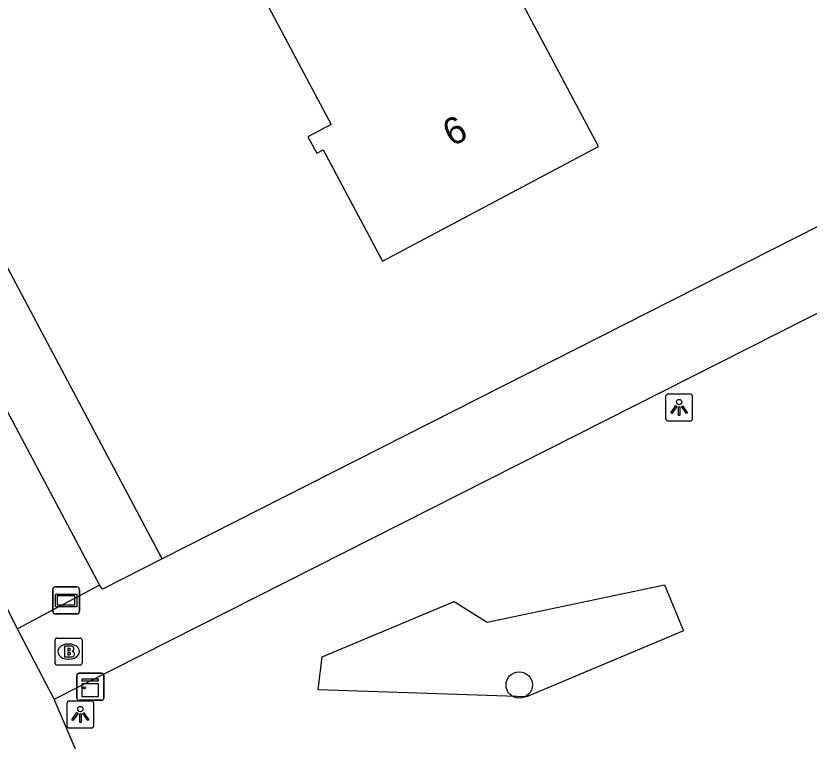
# Model space of a CAD drawing. Extents: x 162417 to 163721, y 384268 to 385416.
# Drawn here: x 163573.8 to 163603.15, y 384788.06 to 384814.9 of the extents above; entities that cross this region are included whole.
import ezdxf

# ---------------------------------------------------------------- set-up
doc = ezdxf.new("R2010")
doc.units = 0
for name, color, linetype in [('IMGEO_Boom', 7, 'Continuous'), ('IMGEO_Brandkraan', 7, 'Continuous'), ('IMGEO_Groenvoorziening', 7, 'Continuous'), ('IMGEO_Kast', 7, 'Continuous'), ('IMGEO_Lichtpunt', 7, 'Continuous'), ('IMGEO_Pand', 7, 'Continuous'), ('IMGEO_Pand_nummerreeks', 7, 'Continuous'), ('IMGEO_Rijbaan_lokaal_gesloten', 7, 'Continuous'), ('IMGEO_Verklikker', 7, 'Continuous'), ('IMGEO_Voetpad_open', 7, 'Continuous')]:
    doc.layers.add(name, color=color, linetype=linetype)

msp = doc.modelspace()

# ---------------------------------------------------------------- linework, layer by layer
at = {"layer": 'IMGEO_Boom'}
msp.add_circle((163592.424, 384790.139), 0.489, dxfattribs=at)
at = {"layer": 'IMGEO_Brandkraan'}
for p, q in [((163575.325, 384791.875), (163576.177, 384791.875)), ((163575.25, 384790.949), (163575.25, 384791.801)), ((163575.738, 384791.655), (163575.763, 384791.655)), ((163576.251, 384791.801), (163576.251, 384790.949)), ((163575.761, 384791.095), (163575.736, 384791.095)), ((163576.177, 384790.875), (163575.325, 384790.875))]:
    msp.add_line(p, q, dxfattribs=at)
for points in [[(163575.325, 384791.875), (163576.177, 384791.875)], [(163575.25, 384790.949), (163575.25, 384791.801)], [(163575.598, 384791.575), (163575.598, 384791.175), (163575.811, 384791.175)], [(163575.829, 384791.575), (163575.598, 384791.575)], [(163576.251, 384791.801), (163576.251, 384790.949)], [(163575.777, 384791.494), (163575.723, 384791.494), (163575.723, 384791.418)], [(163575.723, 384791.418), (163575.776, 384791.418)], [(163575.785, 384791.342), (163575.723, 384791.342), (163575.723, 384791.261)], [(163575.723, 384791.261), (163575.785, 384791.261)], [(163576.177, 384790.875), (163575.325, 384790.875)]]:
    msp.add_lwpolyline(points, dxfattribs=at)
for centre, radius, start, end in [((163575.327, 384791.799), 0.0765, 91.552, 178.448), ((163575.327, 384791.799), 0.0765, 91.552, 178.448), ((163576.175, 384791.799), 0.0765, 1.552, 88.448), ((163576.175, 384791.799), 0.0765, 1.552, 88.448), ((163575.833, 384791.43), 0.145, 59.4692, 91.5367), ((163575.858, 384791.477), 0.0922, 285.5137, 58.1501), ((163575.778, 384791.456), 0.0379, 267.8285, 90.9355), ((163575.786, 384791.301), 0.0404, 269.8759, 90.5077), ((163575.863, 384791.285), 0.105, 301.3115, 78.989), ((163575.817, 384791.426), 0.251, 268.6676, 293.5347), ((163575.327, 384790.951), 0.0765, 181.552, 268.448), ((163575.327, 384790.951), 0.0765, 181.552, 268.448), ((163576.175, 384790.951), 0.0765, 271.552, 358.448), ((163576.175, 384790.951), 0.0765, 271.552, 358.448)]:
    msp.add_arc(centre, radius, start, end, dxfattribs=at)
for centre, major_axis, ratio, start_param, end_param in [((163575.737, 384791.375), (-0.387, 0.002), 0.722429, 4.712389, 7.853982), ((163575.762, 384791.375), (-0.39, 0.002), 0.717154, 1.570796, 4.712389)]:
    msp.add_ellipse(centre, major_axis=major_axis, ratio=ratio, start_param=start_param, end_param=end_param, dxfattribs=at)
at = {"layer": 'IMGEO_Groenvoorziening'}
msp.add_lwpolyline([(163592.689, 384789.696), (163584.983, 384789.965), (163585.127, 384791.183), (163590.02, 384793.225), (163591.241, 384792.459), (163597.802, 384793.844), (163598.502, 384792.145), (163592.689, 384789.696)], dxfattribs=at)
at = {"layer": 'IMGEO_Kast'}
for p, q in [((163576.056, 384789.648), (163576.056, 384790.489)), ((163576.056, 384790.489), (163576.056, 384789.648)), ((163576.131, 384790.573), (163576.972, 384790.573)), ((163576.972, 384790.573), (163576.131, 384790.573)), ((163577.056, 384790.498), (163577.056, 384789.657)), ((163577.056, 384789.657), (163577.056, 384790.498)), ((163576.981, 384789.573), (163576.14, 384789.573)), ((163576.14, 384789.573), (163576.981, 384789.573))]:
    msp.add_line(p, q, dxfattribs=at)
for points in [[(163576.251, 384790.363), (163576.851, 384790.363), (163576.851, 384790.278), (163576.251, 384790.278), (163576.251, 384790.363)], [(163576.251, 384790.188), (163576.851, 384790.188), (163576.851, 384789.699), (163576.251, 384789.699), (163576.251, 384790.188)]]:
    msp.add_lwpolyline(points, dxfattribs=at)
msp.add_circle((163576.335, 384790.037), 0.0377, dxfattribs=at)
for centre, start, end in [((163576.134, 384790.495), 92.4484, 184.2845), ((163576.134, 384790.495), 92.4484, 184.2845), ((163576.978, 384790.495), 2.4484, 94.2845), ((163576.978, 384790.495), 2.4484, 94.2845), ((163576.134, 384789.651), 182.4484, 274.2845), ((163576.134, 384789.651), 182.4484, 274.2845), ((163576.978, 384789.651), 272.4484, 4.2845), ((163576.978, 384789.651), 272.4484, 4.2845)]:
    msp.add_arc(centre, 0.0779, start, end, dxfattribs=at)
at = {"layer": 'IMGEO_Lichtpunt'}
for p, q in [((163597.84, 384800.813), (163597.84, 384800.006)), ((163597.84, 384800.813), (163597.84, 384800.006)), ((163598.742, 384800.908), (163597.934, 384800.908)), ((163598.742, 384800.908), (163597.934, 384800.908)), ((163598.836, 384800.006), (163598.836, 384800.813)), ((163598.836, 384800.006), (163598.836, 384800.813)), ((163597.934, 384799.912), (163598.742, 384799.912)), ((163597.934, 384799.912), (163598.742, 384799.912)), ((163576.59, 384789.546), (163575.782, 384789.546)), ((163576.59, 384789.546), (163575.782, 384789.546)), ((163575.688, 384789.451), (163575.688, 384788.644)), ((163575.688, 384789.451), (163575.688, 384788.644)), ((163576.684, 384788.644), (163576.684, 384789.451)), ((163576.684, 384788.644), (163576.684, 384789.451)), ((163575.782, 384788.55), (163576.59, 384788.55)), ((163575.782, 384788.55), (163576.59, 384788.55))]:
    msp.add_line(p, q, dxfattribs=at)
for points in [[(163598.214, 384800.477), (163598.253, 384800.449), (163598.065, 384800.187), (163598.027, 384800.214), (163598.214, 384800.477)], [(163598.316, 384800.429), (163598.363, 384800.429), (163598.363, 384800.107), (163598.316, 384800.107), (163598.316, 384800.429)], [(163598.426, 384800.449), (163598.464, 384800.476), (163598.651, 384800.214), (163598.612, 384800.186), (163598.426, 384800.449)], [(163576.062, 384789.115), (163576.101, 384789.087), (163575.913, 384788.825), (163575.875, 384788.852), (163576.062, 384789.115)], [(163576.164, 384789.067), (163576.211, 384789.067), (163576.211, 384788.745), (163576.164, 384788.745), (163576.164, 384789.067)], [(163576.274, 384789.087), (163576.312, 384789.114), (163576.499, 384788.852), (163576.46, 384788.824), (163576.274, 384789.087)]]:
    msp.add_lwpolyline(points, dxfattribs=at)
for centre in [(163598.339, 384800.611), (163576.187, 384789.249)]:
    msp.add_circle(centre, 0.0994, dxfattribs=at)
for centre, start, end in [((163597.934, 384800.813), 90, 180), ((163597.934, 384800.813), 90, 180), ((163598.742, 384800.813), 0, 90), ((163598.742, 384800.813), 0, 90), ((163597.934, 384800.006), 180, 270), ((163597.934, 384800.006), 180, 270), ((163598.742, 384800.006), 270, 0), ((163598.742, 384800.006), 270, 360), ((163575.782, 384789.451), 90, 180), ((163575.782, 384789.451), 90, 180), ((163576.59, 384789.451), 0, 90), ((163576.59, 384789.451), 0, 90), ((163575.782, 384788.644), 180, 270), ((163575.782, 384788.644), 180, 270), ((163576.59, 384788.644), 270, 0), ((163576.59, 384788.644), 270, 360)]:
    msp.add_arc(centre, 0.0946, start, end, dxfattribs=at)
at = {"layer": 'IMGEO_Pand'}
msp.add_lwpolyline([(163583.797, 384826.176), (163583.892, 384825.997), (163584.307, 384825.214), (163585.85, 384822.305), (163583.685, 384821.157), (163583.495, 384821.056), (163585.013, 384818.195), (163582.34, 384816.777), (163582.447, 384816.574), (163585.463, 384810.887), (163584.605, 384810.432), (163584.931, 384809.816), (163585.173, 384809.945), (163587.359, 384805.824), (163595.361, 384810.069), (163591.933, 384816.532), (163591.144, 384818.02), (163594.128, 384819.603)], dxfattribs=at)
at = {"layer": 'IMGEO_Rijbaan_lokaal_gesloten'}
for points in [[(163573.858, 384792.219), (163571.704, 384796.445), (163565.334, 384808.395)], [(163575.222, 384789.612), (163573.909, 384792.119), (163573.858, 384792.219)], [(163577.57, 384783.198), (163577.885, 384783.374), (163575.222, 384789.612)]]:
    msp.add_lwpolyline(points, dxfattribs=at)
at = {"layer": 'IMGEO_Verklikker'}
for p, q in [((163575.164, 384792.868), (163575.164, 384793.668)), ((163575.164, 384793.668), (163575.164, 384792.868)), ((163575.264, 384793.768), (163576.054, 384793.768)), ((163576.054, 384793.768), (163575.264, 384793.768)), ((163576.154, 384793.668), (163576.154, 384792.868)), ((163576.154, 384792.868), (163576.154, 384793.668)), ((163576.054, 384792.768), (163575.264, 384792.768)), ((163575.264, 384792.768), (163576.054, 384792.768))]:
    msp.add_line(p, q, dxfattribs=at)
for points in [[(163575.265, 384793.5), (163576.053, 384793.5), (163576.053, 384793.036), (163575.265, 384793.036), (163575.265, 384793.5)], [(163575.33, 384793.435), (163575.33, 384793.101), (163575.988, 384793.101), (163575.988, 384793.435), (163575.33, 384793.435)]]:
    msp.add_lwpolyline(points, dxfattribs=at)
for centre, start, end in [((163575.264, 384793.668), 90, 180), ((163575.264, 384793.668), 90, 180), ((163576.054, 384793.668), 0, 90), ((163576.054, 384793.668), 360, 90), ((163575.264, 384792.868), 180, 270), ((163575.264, 384792.868), 180, 270), ((163576.054, 384792.868), 270, 0), ((163576.054, 384792.868), 270, 0)]:
    msp.add_arc(centre, 0.1, start, end, dxfattribs=at)
at = {"layer": 'IMGEO_Voetpad_open'}
for points in [[(163579.211, 384794.807), (163552.107, 384845.87), (163518.056, 384909.494), (163515.928, 384908.35), (163515.734, 384908.25)], [(163644.977, 384828.162), (163641.486, 384826.348), (163641.667, 384825.959), (163626.635, 384818.288), (163626.367, 384818.629), (163618.849, 384814.904), (163579.211, 384794.807)], [(163575.222, 384789.612), (163621.295, 384812.929), (163628.147, 384799.526)], [(163567.994, 384810.595), (163576.893, 384793.832)], [(163579.211, 384794.807), (163577.006, 384793.682), (163576.893, 384793.832)], [(163576.893, 384793.832), (163573.858, 384792.219)]]:
    msp.add_lwpolyline(points, dxfattribs=at)

# ---------------------------------------------------------------- texts
at = {"layer": 'IMGEO_Pand_nummerreeks'}
msp.add_text('6', height=1, rotation=27.9432, dxfattribs=at).set_placement((163589.936, 384810.043))

doc.saveas('drawing.dxf')
